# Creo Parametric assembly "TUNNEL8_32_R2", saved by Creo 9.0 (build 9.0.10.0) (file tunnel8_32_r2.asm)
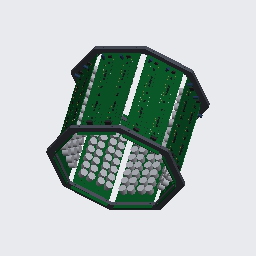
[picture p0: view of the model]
Units: millimeter Newton Second (mmNs); MM, TONNE, SECS

Created from: XX_MMNS_ASM_DESIGN_ABS.ASM

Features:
  1. datum plane "ASM_RIGHT"
  2. datum plane "ASM_TOP"
  3. datum plane "ASM_FRONT"
  4. coordinate system
  5. coordinate system
  6. component "PANEL32_R2"
  7. coordinate system
  8. component "PANEL32_R2"
  9. coordinate system
  10. component "PANEL32_R2"
  11. coordinate system
  12. component "PANEL32_R2"
  13. coordinate system
  14. component "PANEL32_R2"
  15. coordinate system
  16. component "PANEL32_R2"
  17. coordinate system
  18. component "PANEL32_R2"
  19. coordinate system
  20. component "PANEL32_R2"
  21. coordinate system
  22. component "RING8_32_R2"
  23. coordinate system
  24. component "RING8_32_R2"

Other named items: ACS0, ACS1, ACS2, ACS3, ACS4, ACS5, ACS6, ACS7, ACS8, ACS9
